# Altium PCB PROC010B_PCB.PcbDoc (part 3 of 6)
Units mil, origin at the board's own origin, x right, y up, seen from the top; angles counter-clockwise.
Board outline 3180 x 2565 mil, 6 copper layers (TOP, L2, L3, L4, L5, BOTTOM), stack 55.54 mil thick; 362 components, 264 nets, 1248 pads, 1144 vias.
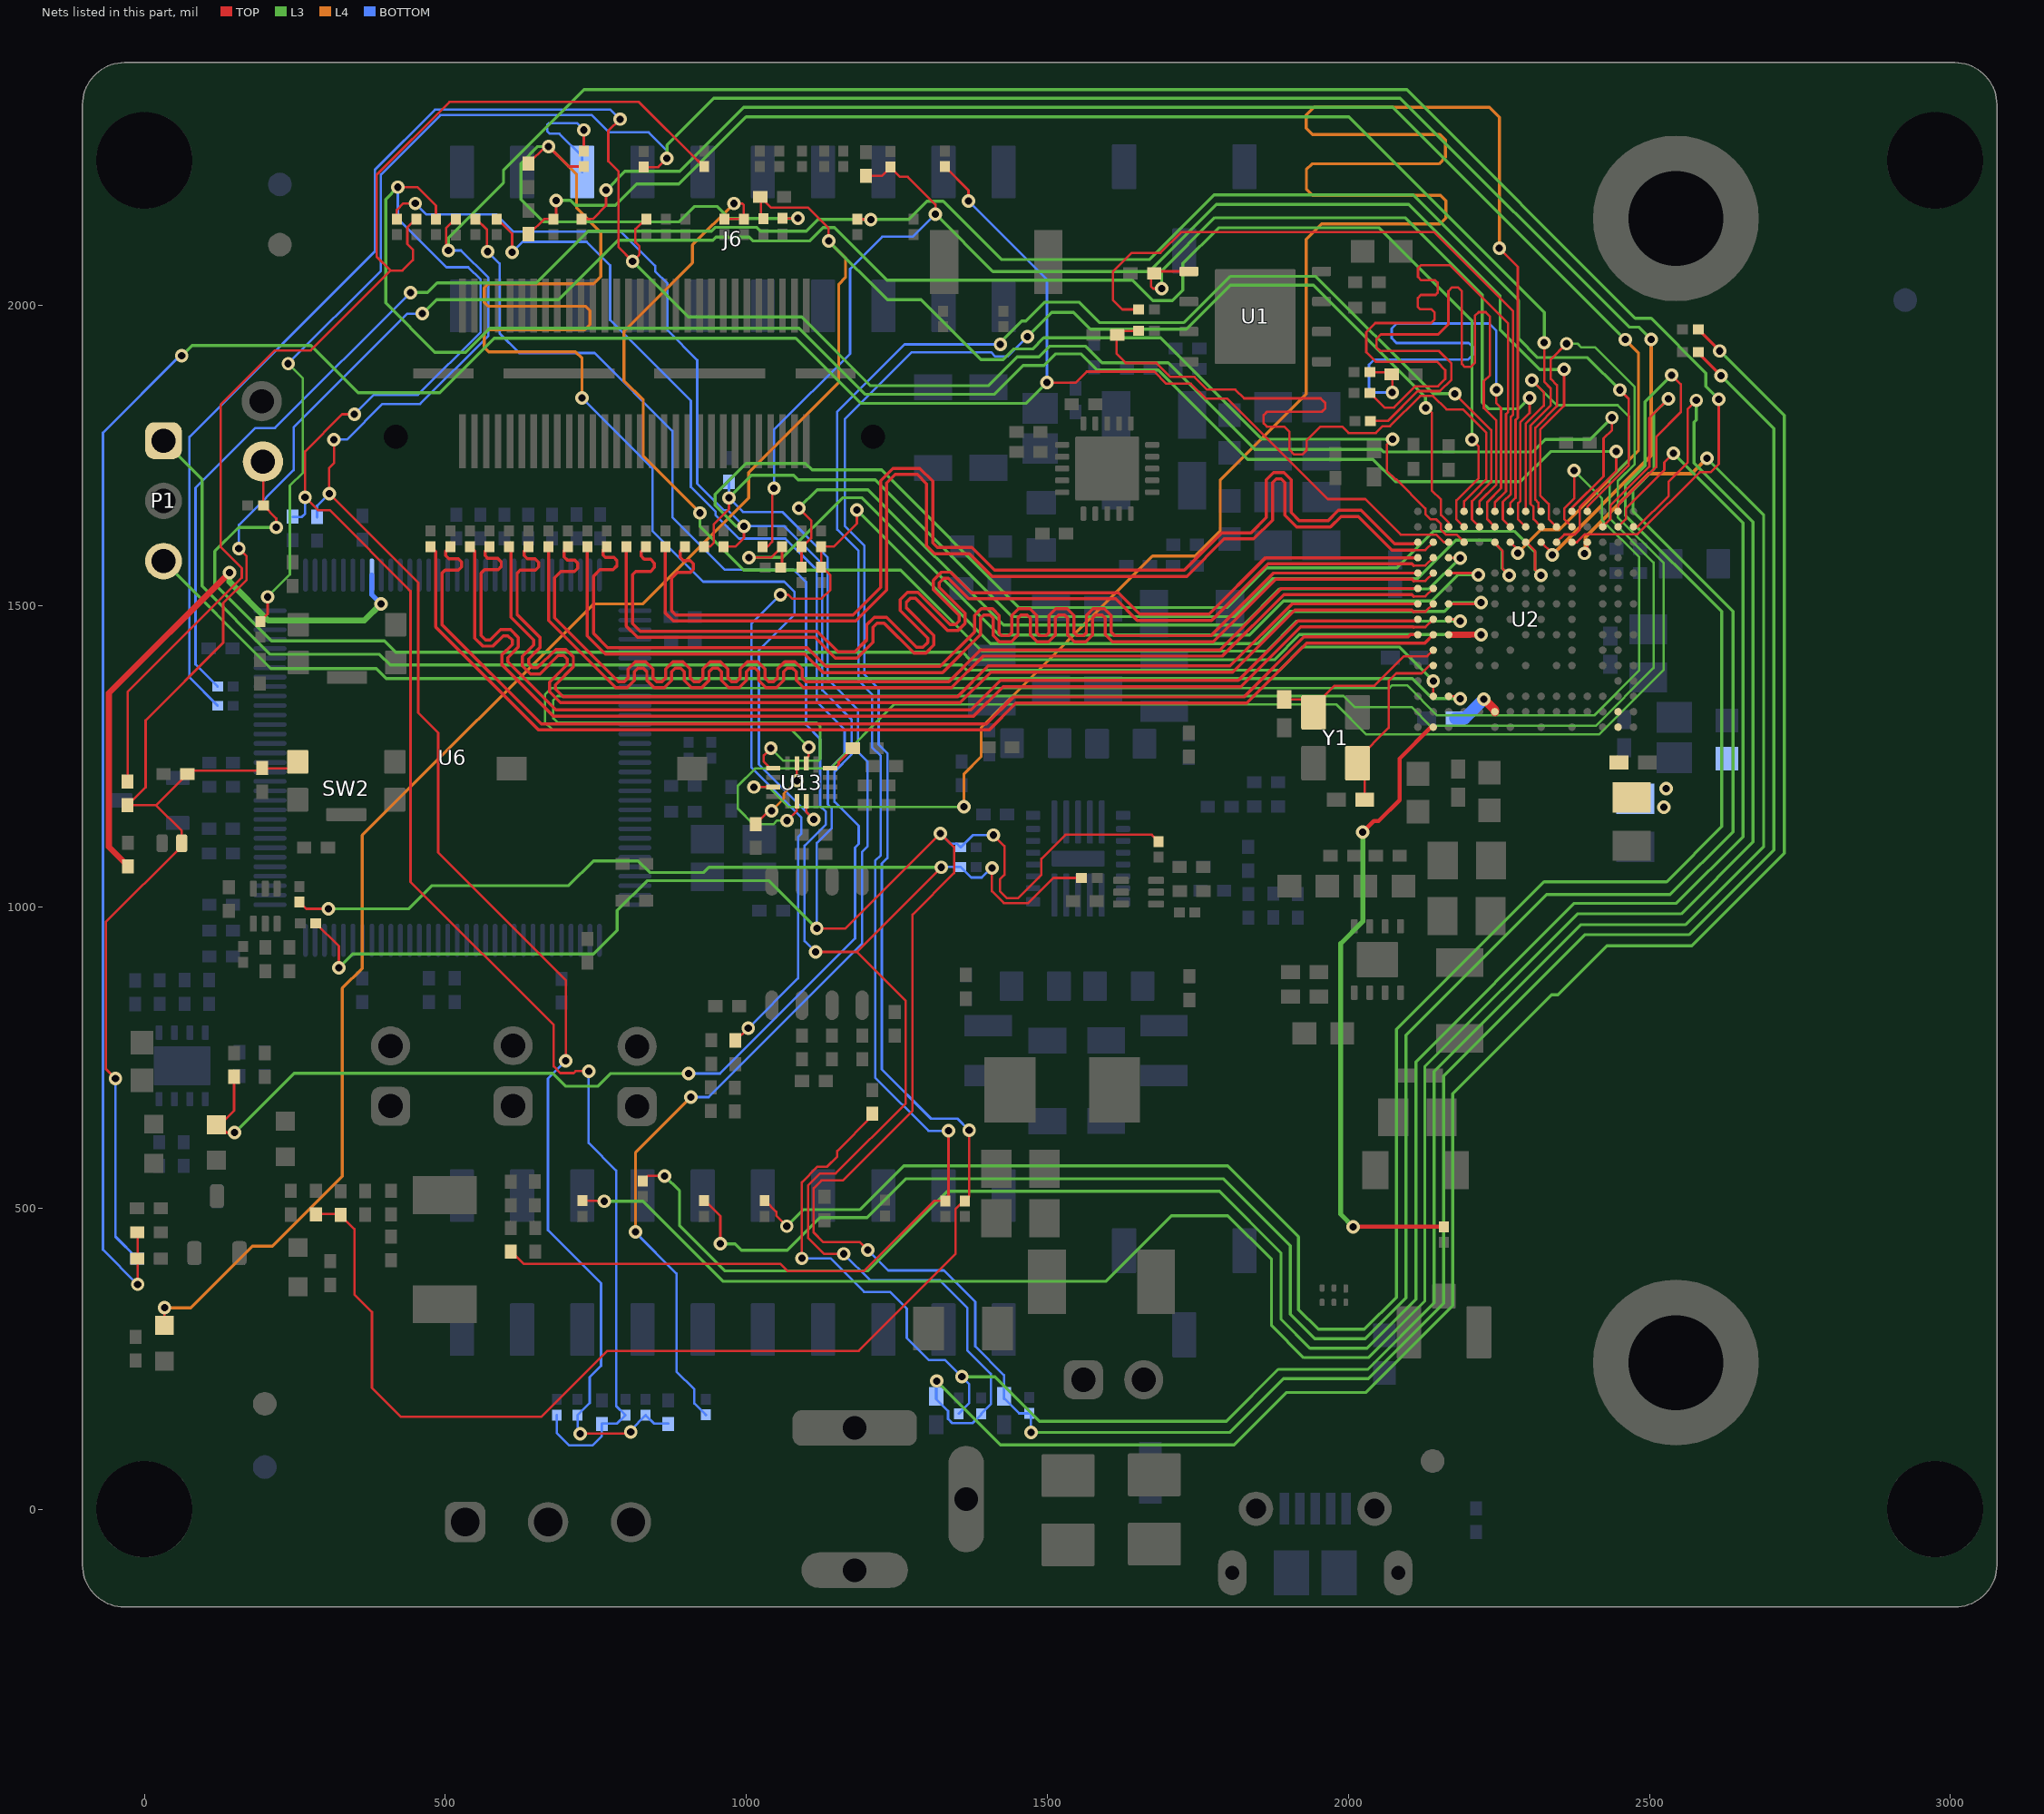
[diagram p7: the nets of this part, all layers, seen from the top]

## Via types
v1: diameter 22.4, hole 12.2, TOP to BOTTOM, tented both sides, 621 vias
v2: diameter 13.77/15.74 (per signal layer), hole 5.9, TOP to L2, tented top, 508 vias
v3: diameter 19.68, hole 7.87, TOP to BOTTOM, tented top, 7 vias
v4: diameter 19.68, hole 7.87, TOP to BOTTOM, 4 vias
v5: diameter 19.68, hole 7.87, TOP to BOTTOM, tented both sides, 3 vias
v6: diameter 19.68, hole 7.87, TOP to BOTTOM, tented bottom, 1 vias

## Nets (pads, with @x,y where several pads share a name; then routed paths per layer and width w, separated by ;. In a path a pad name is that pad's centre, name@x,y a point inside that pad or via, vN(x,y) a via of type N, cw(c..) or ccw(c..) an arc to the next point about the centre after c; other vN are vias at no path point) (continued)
AR_ANAMUX: P1.3 U2.C13 | length 2270.4
  TOP w4: U2.C13@2166.6,1349.95 2182.2,1349.95 v1(2185.95,1346.2)
  L3 w5: P1.3@31.27,1575.06 210.06,1396.27 385.08,1396.27 401.95,1379.4 2106.19,1379.4 2139.39,1346.2 v1(2185.95,1346.2)
AR_ANATEST1: R104.2 U2.P1 | length 3822.8
  TOP w4: R104.2@727.75,512.27 754,512.27 754,511.5 v1(764,511.5) ; U2.P1@2473.68,1631.44 2480.42,1631.44 2532,1683.02 2532,1706.66 2563.69,1738.34 2563.69,1827.19 v1(2578,1841.5)
  L3 w5: v1(764,511.5) 828.16,511.5 961.06,378.61 1597.42,378.61 1706.36,487.55 1799.89,487.55 1872.41,415.03 1872.41,305.11 1925.67,251.84 2032.92,251.84 2126.97,345.89 2126.97,735.23 2380.42,988.68 2552.76,988.68 2672,1107.92 2672,1639.42 2574.18,1737.25 2574.18,1805.3 2578,1809.13 v1(2578,1841.5)
AR_ANATEST2: R94.2 U2.P2 | length 3584.5
  TOP w4: R94.2@828.25,545.27 836.48,553.5 v1(864,553.5) ; U2.P2@2448.09,1631.44 2460.95,1644.3 2460.95,1661.98 2524.86,1725.89 2524.86,1738.36 v1(2540,1753.5)
  L3 w5: v1(864,553.5) 889.05,528.45 889.05,470.46 963.59,395.92 1202.19,395.92 1334.16,527.89 1786.02,527.89 1888.11,425.8 1888.11,315.63 1936.32,267.42 2030.95,267.42 2112.37,348.84 2112.37,743.08 2375.47,1006.18 2545.11,1006.18 2655.39,1116.46 2655.39,1638.11 v1(2540,1753.5)
AR_ANATEST3: R105.2 U2.P3 | length 3670
  TOP w4: R105.2@929.75,512.27 931.28,512.27 956.86,486.69 v1(956.86,440.79) ; U2.P3@2422.5,1631.44 2435.45,1644.39 2435.45,1666.95 2500,1731.5 2500,1812.5 v1(2531.5,1844)
  L3 w5: v1(956.86,440.79) 981.11,440.79 991.74,430.16 1068.11,430.16 1122.53,484.58 1200.35,484.58 1264.48,548.71 1792.67,548.71 1903.68,437.69 1903.68,323.69 1944.21,283.16 2028.16,283.16 2095.88,350.87 2095.88,787.34 2329.2,1020.66 2534.53,1020.66 2638.75,1124.88 2638.75,1491.26 2472.85,1657.16 2472.85,1692.35 2507.49,1726.99 2507.49,1819.99 v1(2531.5,1844)
AR_ANATEST4: R106.2 U2.R2 | length 3566.4
  TOP w4: R106.2@1030.25,512.27 1031.49,512.27 1049.72,494.04 1049.72,487.5 v1(1067.22,470) ; U2.R2@2448.09,1657.03 2448.09,1667.59 2511.41,1730.91 2511.41,1780.91 2552.3,1821.8 2552.3,1868.2 v1(2537,1883.5)
  L3 w5: v1(1067.22,470) 1094.81,497.59 1188.92,497.59 1261.58,570.25 1799.44,570.25 1917.36,452.33 1917.36,331.5 1950.06,298.8 2026.73,298.8 2079.84,351.91 2079.84,796.88 2325.09,1042.12 2528.62,1042.12 2620.05,1133.55 2620.05,1490.89 2459.96,1650.98 2459.96,1699.98 2492.58,1732.6 2492.58,1839.08 v1(2537,1883.5)
AR_BSS_LOGGER: R31.1 R135.1 U2.R4 | length 3430.8
  TOP w4: U2.R4@2396.91,1657.03 2396.91,1664.41 2465.49,1732.99 2465.49,1844.4 v1(2451.13,1858.76)
  TOP w5: R31.1@1182.65,2139.15 1185.37,2141.87 v1(1206.66,2141.87)
  L3 w5: v1(442,2020.5) 470.43,2020.5 486.56,2036.63 651.36,2036.63 736.99,2122.26 942.38,2122.26 949.03,2128.9 1016.89,2128.9 1023.53,2122.26 1099.51,2122.26 1119.12,2141.87 v1(1206.66,2141.87) 1269.96,2141.87 1300.19,2172.1 1326.8,2172.1 1423.44,2075.45 1669.77,2075.45 1776.94,2182.62 2107.47,2182.62 2282.52,2007.58 2282.52,1944.35 2314.39,1912.48 2397.42,1912.48 v1(2451.13,1858.76)
  BOTTOM w4: R135.1@121.79,1366.19 85,1402.98 85,1696.18 184.32,1795.5 217,1795.5 v1(442,2020.5)
AR_CS1: U2.R7 U13.10 | length 2799.2
  TOP w4: v1(1067.5,1143.73) 1083.98,1160.21 U13.10@1083.98,1175.71 ; U2.R7@2320.14,1657.03 2315.55,1661.63 2315.55,1671.77 2310.55,1676.77 2310.55,1796.15 2346.47,1832.07 2346.47,1866.84 2336.3,1877.01 2336.3,1909.5 v1(2362.38,1935.58)
  L3 w4: v1(1067.5,1143.73) 1051.19,1143.73 1045.05,1137.59 1011.49,1137.59 985.8,1163.28 985.8,1201.38 1014.57,1230.15 1139.06,1230.15 1245.47,1336.55 1980.09,1336.55 2029.86,1286.79 2416.28,1286.79 2523.8,1394.31 2523.8,1571.37 2447.53,1647.63 2447.53,1707.3 2475.65,1735.41 2475.65,1863.92 2410.04,1929.53 2387.15,1929.53 2381.1,1935.58 v1(2362.38,1935.58)
AR_GPIO_0: R164.1 R177.2 U2.N4 | length 3718.2
  TOP w4: v1(1092.13,416.62) 1092.13,542.93 1118.2,569 1134.25,569 1150.96,585.71 1150.96,594.81 1209.5,653.36 R177.2@1209.5,656.88 ; v1(2392.34,1587.4) 2396.91,1591.97 U2.N4@2396.91,1605.85
  L3 w5: v1(1358,220) 1413,220 1487.1,145.9 1797.11,145.9 1883.52,232.31 2032.28,232.31 2142.6,342.63 2142.6,727.18 2386.2,970.78 2560.31,970.78 2689.9,1100.38 2689.9,1650.98 v1(2595.65,1745.24)
  L4 w6: v1(2392.34,1587.4) 2394,1589.06 2394,1613.96 2499.54,1719.5 2569.91,1719.5 v1(2595.65,1745.24)
  BOTTOM w4: v1(1092.13,416.62) 1139.72,416.62 1195.4,360.94 1238.59,360.94 1266.44,333.09 1266.44,284.55 1302.99,248 1330,248 v1(1358,220) 1370,208 1370,175.98 R164.1@1352.75,158.73
AR_GPIO_1: R9.2 R72.2 U2.N7 | length 3760.8
  TOP w4: R72.2@192.5,1474.24 204.83,1486.57 v1(204.83,1515.16) ; R9.2@829.75,2228.73 853.51,2228.73 v1(868.03,2243.25) ; U2.N7@2320.14,1605.85 2338.45,1587.54 v1(2338.45,1585.1)
  L3 w4: v1(204.83,1515.16) 241.82,1552.15 241.82,1700.01 263.32,1721.51 263.32,1878.18 v1(239,1902.5)
  L3 w5: v1(868.03,2243.25) 868.03,2265.26 945.86,2343.08 2086.2,2343.08 2466.13,1963.16 2482.34,1963.16 v1(2503,1942.5)
  L4 w6: v1(2338.45,1585.1) 2503,1749.65 v1(2503,1942.5)
  BOTTOM w4: v1(239,1902.5) 393,2056.5 393,2216.5 491.72,2315.22 743.28,2315.22 772,2286.5 838,2286.5 868.03,2256.47 v1(868.03,2243.25) 864.75,2243.25 v1@861,2239.5
AR_GPIO_2: R8.2 R110.2 R116.1 U2.N13 | length 4502.3
  TOP w4: R110.2@-11.18,459.77 -11.12,459.71 v1(-11.12,373.5) ; R8.2@1329.55,2229.73 1369,2190.28 v1(1369,2172.5) ; v1(1499.21,1871.03) 1547.26,1871.03 1565.47,1889.24 1677.58,1889.24 1697.56,1869.26 1738.21,1869.26 1763.01,1844.46 1798.79,1844.46 1965.71,1677.54 2027.96,1677.54 2087,1618.5 2146.1,1618.5 2158.75,1605.85 U2.N13@2166.6,1605.85
  L3 w5: v1(62,1915.5) 79.02,1932.52 276.98,1932.52 355.12,1854.38 490.88,1854.38 581.05,1944.55 1081.95,1944.55 1189.89,1836.61 1464.8,1836.61 v1(1499.21,1871.03)
  BOTTOM w4: v1(-11.12,373.5) -68.67,431.05 -68.67,1787.83 59,1915.5 v1(62,1915.5) ; v1(1369,2172.5) 1499.21,2042.29 v1(1499.21,1871.03)
AR_HOSTINTR1: R10.2 R13.2 R64.2 U2.P6 | length 2434.7
  TOP w4: R64.2@1026.61,1598.73 1035.23,1598.73 1043,1606.5 1043,1692.5 v1(1046,1695.5) ; R13.2@1198.4,2214.36 1224.88,2214.36 R10.2@1239.25,2228.73 1255.34,2212.64 1268.02,2212.64 1314.1,2166.56 v1(1314.1,2150.9) ; U2.P6@2345.73,1631.44 2332.91,1644.26 2332.91,1669.44 2318.55,1683.8 2318.55,1792.83 2358.19,1832.48 v1(2358.19,1892.76)
  L3 w5: v1(1314.1,2150.9) 1409.62,2055.38 1669.06,2055.38 1780.66,2166.98 2100.41,2166.98 2252.01,2015.37 2252.01,1958.79 2318.05,1892.76 v1(2358.19,1892.76)
  BOTTOM w4: v1(1046,1695.5) 1046,1792.5 1172.2,1918.7 1172.2,2059.74 1225.75,2113.29 1276.49,2113.29 v1(1314.1,2150.9)
AR_LVDS_VALID_N: R60.2 U2.N14 | length 1930.5
  TOP w4: 2108.58,1592.91 2128.07,1592.91 U2.N14@2141.01,1605.85
  TOP w5.2: R60.2@865.55,1598.73 865.55,1487.96 878.58,1474.93 1181.43,1474.93 1233.11,1526.61 1233.11,1704.06 1247.51,1718.46 1283.9,1718.46 1299.44,1702.92 1299.44,1600.59 1313.11,1586.92 1370.46,1586.92 1408.08,1549.3 1731.83,1549.3 1793.84,1611.31 1842.55,1611.31 1873.93,1642.69 1873.93,1705.01 1880.02,1711.1 1888.64,1711.1 1894.73,1705.01 1894.73,1650.87 1914.39,1631.21 1970.21,1631.21 1987.71,1648.71 2016.79,1648.71 2072.59,1592.91 2108.58,1592.91
AR_LVDS_VALID_P: R61.2 U2.N15 | length 1930.8
  TOP w5.2: R61.2@897.75,1598.73 890,1590.98 890,1580.5 895,1575.5 906.8,1575.5 912,1570.3 912,1560.7 906.8,1555.5 885,1555.5 875.75,1546.25 875.75,1492.19 882.81,1485.13 1177.2,1485.13 1222.91,1530.84 1222.91,1708.28 1243.29,1728.66 1288.12,1728.66 1309.64,1707.14 1309.64,1604.82 1317.34,1597.12 1374.69,1597.12 1412.31,1559.5 1727.61,1559.5 1789.61,1621.51 1838.33,1621.51 1863.73,1646.91 1863.73,1709.24 1875.79,1721.3 1892.87,1721.3 1904.93,1709.24 1904.93,1655.1 1918.62,1641.41 1965.98,1641.41 1983.48,1658.91 2021.02,1658.91 2076.82,1603.11 2108.58,1603.11 2111.32,1605.85 U2.N15@2115.42,1605.85
AR_LVDSCSI0_N: R48.2 U2.G14 | length 1930.5
  TOP w5.2: R48.2@475.61,1598.73 484,1590.34 484,1465.08 655.05,1294.04 1402.98,1294.04 1447.73,1338.79 1830.98,1338.79 1930.51,1438.32 2127.02,1438.32 U2.G14@2141.01,1452.31
AR_LVDSCSI0_P: R49.2 U2.G15 | length 1930.6
  TOP w5.2: R49.2@508.25,1598.73 500.58,1591.06 500.58,1583.7 505.78,1578.5 521.8,1578.5 527,1573.3 527,1564.7 521.8,1559.5 499.4,1559.5 494.2,1554.3 494.2,1469.31 659.27,1304.24 1398.75,1304.24 1443.5,1348.99 1826.76,1348.99 1926.29,1448.52 2099.22,1448.52 2103.01,1452.31 U2.G15@2115.42,1452.31
AR_LVDSCSI1_N: R50.2 U2.H14 | length 1931
  TOP w4: 2108.32,1464.96 2128.07,1464.96 U2.H14@2141.01,1477.9
  TOP w5.2: R50.2@540.75,1598.73 541.77,1598.73 549,1591.5 549,1446.77 562.37,1433.4 578.91,1433.4 596.01,1450.5 604.01,1450.5 611.06,1443.45 611.06,1436.09 593.64,1418.67 593.64,1402.87 679.21,1317.3 1377.61,1317.3 1426.4,1366.09 1821.53,1366.09 1920.74,1465.3 2107.98,1465.3 2108.32,1464.96
AR_LVDSCSI1_P: R51.2 U2.H15 | length 1931
  TOP w5.2: R51.2@573.25,1598.73 566,1591.48 566,1583.5 570,1579.5 586.43,1579.5 592.87,1573.06 592.87,1565.7 587.67,1560.5 565,1560.5 559.2,1554.7 559.2,1450.99 566.59,1443.6 574.68,1443.6 591.78,1460.7 608.24,1460.7 621.26,1447.68 621.26,1431.86 603.84,1414.44 603.84,1407.1 683.44,1327.5 1373.39,1327.5 1422.17,1376.28 1817.3,1376.28 1916.52,1475.5 2113.02,1475.5 U2.H15@2115.42,1477.9
AR_LVDSCSI2_N: R54.2 U2.K14 | length 1930.8
  TOP w4: 2108.32,1516.14 2128.07,1516.14 U2.K14@2141.01,1529.08
  TOP w5.2: R54.2@671.35,1598.73 671.35,1476.15 783.2,1364.3 801.86,1364.3 813.92,1376.36 813.92,1391.01 820.01,1397.1 828.63,1397.1 834.72,1391.01 834.72,1376.36 846.78,1364.3 863.86,1364.3 875.92,1376.36 875.92,1391.01 882.01,1397.1 890.63,1397.1 896.72,1391.01 896.72,1376.36 908.78,1364.3 925.86,1364.3 937.92,1376.36 937.92,1391.01 944.01,1397.1 952.63,1397.1 958.72,1391.01 958.72,1376.36 970.78,1364.3 987.86,1364.3 999.92,1376.36 999.92,1391.01 1006.01,1397.1 1014.63,1397.1 1020.72,1391.01 1020.72,1376.36 1032.78,1364.3 1049.86,1364.3 1061.92,1376.36 1061.92,1391.01 1068.01,1397.1 1076.63,1397.1 1082.72,1391.01 1082.72,1376.36 1094.78,1364.3 1340.79,1364.3 1393.29,1416.8 1790.68,1416.8 1892.76,1518.88 2105.58,1518.88 2108.32,1516.14
AR_LVDSCSI2_P: R55.2 U2.K15 | length 1930.8
  TOP w5.2: R55.2@703.85,1598.73 697,1591.88 697,1581.7 702.2,1576.5 714.8,1576.5 720,1571.3 720,1562.7 714.8,1557.5 692,1557.5 681.55,1547.05 681.55,1480.38 787.43,1374.5 797.63,1374.5 803.72,1380.59 803.72,1395.24 815.78,1407.3 832.86,1407.3 844.92,1395.24 844.92,1380.59 851.01,1374.5 859.63,1374.5 865.72,1380.59 865.72,1395.24 877.78,1407.3 894.86,1407.3 906.92,1395.24 906.92,1380.59 913.01,1374.5 921.63,1374.5 927.72,1380.59 927.72,1395.24 939.78,1407.3 956.86,1407.3 968.92,1395.24 968.92,1380.59 975.01,1374.5 983.63,1374.5 989.72,1380.59 989.72,1395.24 1001.78,1407.3 1018.86,1407.3 1030.92,1395.24 1030.92,1380.59 1037.01,1374.5 1045.63,1374.5 1051.72,1380.59 1051.72,1395.24 1063.78,1407.3 1080.86,1407.3 1092.92,1395.24 1092.92,1380.59 1099.01,1374.5 1336.57,1374.5 1389.07,1427 1786.46,1427 1888.54,1529.08 U2.K15@2115.42,1529.08
AR_LVDSCSI3_N: R56.2 U2.L14 | length 1930.7
  TOP w4: 2108.32,1541.73 2128.07,1541.73 U2.L14@2141.01,1554.67
  TOP w5.2: R56.2@735.75,1598.73 735.76,1450.3 765.56,1420.5 1096.79,1420.5 1127.79,1389.5 1326.03,1389.5 1389.09,1452.56 1389.09,1480.1 1394.29,1485.3 1404.69,1485.3 1409.89,1480.1 1409.89,1450.81 1420.2,1440.5 1439.92,1440.5 1451.09,1451.67 1451.09,1480.1 1456.29,1485.3 1466.69,1485.3 1471.89,1480.1 1471.89,1451.68 1483.07,1440.5 1501.91,1440.5 1513.09,1451.68 1513.09,1480.1 1518.29,1485.3 1528.69,1485.3 1533.89,1480.1 1533.89,1451.67 1545.06,1440.5 1563.91,1440.5 1575.09,1451.68 1575.09,1480.1 1580.29,1485.3 1590.69,1485.3 1595.89,1480.1 1595.89,1452.56 1607.95,1440.5 1775.76,1440.5 1879.73,1544.47 2105.58,1544.47 2108.32,1541.73
AR_LVDSCSI3_P: R57.2 U2.L15 | length 1930.7
  TOP w5.2: R57.2@768.05,1598.73 762,1592.68 762,1584.5 766,1580.5 779.8,1580.5 785,1575.3 785,1566.7 778.8,1560.5 757,1560.5 745.96,1549.46 745.96,1454.53 769.79,1430.7 1101.02,1430.7 1132.02,1399.7 1321.8,1399.7 1378.89,1456.79 1378.89,1484.33 1390.06,1495.5 1408.92,1495.5 1420.09,1484.33 1420.09,1455.04 1424.43,1450.7 1435.69,1450.7 1440.89,1455.9 1440.89,1484.33 1452.06,1495.5 1470.92,1495.5 1482.09,1484.33 1482.09,1455.91 1487.3,1450.7 1497.68,1450.7 1502.89,1455.91 1502.89,1484.33 1514.06,1495.5 1532.92,1495.5 1544.09,1484.33 1544.09,1455.9 1549.29,1450.7 1559.68,1450.7 1564.89,1455.91 1564.89,1484.33 1576.06,1495.5 1594.92,1495.5 1606.09,1484.33 1606.09,1456.79 1612.18,1450.7 1771.53,1450.7 1875.5,1554.67 U2.L15@2115.42,1554.67
AR_LVDSCSI_CLK_N: R52.2 U2.J14 | length 1930.5
  TOP w4: 2108.32,1490.55 2128.07,1490.55 U2.J14@2141.01,1503.49
  TOP w5.2: R52.2@605.75,1598.73 609,1595.48 609,1481.5 646.75,1443.75 646.75,1435.13 627.95,1416.33 627.95,1400.51 641.29,1387.17 657.11,1387.17 687.72,1417.78 696.28,1417.78 702.43,1411.63 702.43,1403.07 672.83,1373.47 672.83,1357.67 691.2,1339.3 1355.15,1339.3 1405.98,1390.12 1807.86,1390.12 1911.03,1493.29 2105.58,1493.29 2108.32,1490.55
AR_LVDSCSI_CLK_P: R53.2 U2.J15 | length 1930.2
  TOP w5.2: R53.2@638.25,1598.73 631,1591.48 631,1583.7 636.2,1578.5 648.78,1578.5 655,1572.28 655,1564.7 649.8,1559.5 624.4,1559.5 619.2,1554.3 619.2,1485.73 656.95,1447.98 656.95,1430.9 638.15,1412.1 638.15,1404.74 645.52,1397.37 652.88,1397.37 683.49,1427.98 700.51,1427.98 712.63,1415.86 712.63,1398.84 683.03,1369.24 683.03,1361.9 695.43,1349.5 1350.93,1349.5 1401.75,1400.32 1803.64,1400.32 1906.8,1503.49 U2.J15@2115.42,1503.49
AR_LVDSCSI_FRCLK_N: R58.2 U2.M14 | length 1930.8
  TOP w4: 2108.32,1567.32 2128.07,1567.32 U2.M14@2141.01,1580.26
  TOP w5.2: R58.2@800.55,1598.73 800.55,1466.51 819.26,1447.8 1113.7,1447.8 1148,1413.5 1184.14,1413.5 1210.39,1439.74 1210.39,1464.72 1216.94,1471.27 1228.79,1471.27 1277.87,1422.19 ; 1277.88,1422.19 1278.69,1421.38 1297.65,1421.38 1311.47,1435.2 1311.47,1451.01 1310.59,1451.89 1265.73,1496.76 1265.73,1506.32 1271.96,1512.55 1280.96,1512.55 1334.46,1459.05 1351.54,1459.05 1363.6,1471.11 1363.6,1488.19 1320.53,1531.26 1320.53,1538.39 1328.13,1545.99 1335.26,1545.99 1369.33,1511.92 1613.53,1511.92 1649.29,1476.16 1772.79,1476.16 1866.69,1570.06 2105.58,1570.06 2108.32,1567.32
AR_LVDSCSI_FRCLK_P: R59.2 U2.M15 | length 1930.3
  TOP w5.2: R59.2@833.05,1598.73 825,1590.68 825,1582.7 830.2,1577.5 840.92,1577.5 847.24,1571.18 847.24,1563.82 840.92,1557.5 816,1557.5 810.75,1552.25 810.75,1470.74 823.49,1457.99 1117.93,1457.99 1152.23,1423.7 1179.92,1423.7 1200.19,1443.97 1200.19,1468.94 1212.72,1481.47 1233.02,1481.47 1282.91,1431.58 1293.43,1431.58 1301.28,1439.42 1301.28,1446.78 1255.53,1492.53 1255.53,1510.54 1267.74,1522.75 1285.19,1522.75 1338.69,1469.25 1347.31,1469.25 1353.4,1475.34 1353.4,1483.96 1310.33,1527.03 1310.33,1542.61 1323.91,1556.19 1339.49,1556.19 1373.56,1522.12 1617.76,1522.12 1653.52,1486.36 1768.56,1486.36 1862.46,1580.26 U2.M15@2115.42,1580.26
AR_MCUCLKOUT: R25.1 U2.N9 | length 2473.2
  TOP w4: R25.1@726.25,2142.71 744.9,2142.71 767,2164.81 v1(767,2190.5) ; U2.N9@2268.96,1605.85 2281.19,1593.62 v1(2281.19,1587.85)
  L3 w5: v1(767,2190.5) 798.36,2221.86 889.32,2221.86 995.82,2328.37 2074.05,2328.37 v1(2459.96,1942.46)
  L4 w5: v1(2281.19,1587.85) 2319.84,1626.5 2350.43,1626.5 2481.77,1757.84 2481.77,1920.65 v1(2459.96,1942.46)
AR_MISO1: U2.P5 U13.2 | length 2887.4
  TOP w4: U13.2@1099.73,1238.71 1099.73,1247.06 1103.57,1250.89 v1(1103.57,1265.52) ; U2.P5@2371.32,1631.44 2358.82,1643.94 2358.82,1662.32 2375,1678.5 v1(2375,1725)
  L3 w4: v1(1103.57,1265.52) 1074.7,1294.39 677.98,1294.39 665.41,1306.96 665.41,1352.64 676.51,1363.74 2068.2,1363.74 2072.78,1368.32 2097.46,1368.32 2147.38,1318.4 2408.4,1318.4 2483.17,1393.17 2483.17,1581.06 2421.18,1643.05 2421.18,1678.82 v1(2375,1725)
AR_MOSI1: U2.R8 U13.5 | length 3449.3
  TOP w4: v1(1040.7,1263.94) 1028.78,1252.02 1028.78,1241.41 1039.36,1230.83 U13.5@1044.61,1230.83 ; U2.R8@2294.55,1657.03 2294.55,1802.77 2324.54,1832.77 2324.54,1855.08 v1(2304.72,1874.9)
  L3 w4: v1(1040.7,1263.94) 1061.69,1242.95 1119.65,1242.95 1122.59,1245.9 1122.59,1300.34 1116.76,1306.18 686.78,1306.18 679.28,1313.68 679.28,1343.46 686.33,1350.51 1991.94,1350.51 2010.64,1331.81 2105.54,1331.81 2136.32,1301.02 2411.06,1301.02 2506.93,1396.89 2506.93,1572.14 2434.1,1644.97 2434.1,1711.17 2465.94,1743.02 2465.94,1814.9 2447.33,1833.51 2346.11,1833.51 v1(2304.72,1874.9)
AR_MSS_LOGGER: R26.1 R136.1 U2.R5 | length 3858.3
  TOP w4: v1(790,2308.5) 770.75,2289.25 770.75,2238.75 787.37,2222.13 787.37,2096.13 v1(811,2072.5) 822.45,2083.95 822.45,2097.21 815.72,2103.95 815.72,2125.93 832.5,2142.71 R26.1@834.11,2142.71 ; U2.R5@2371.32,1657.03 2371.32,1662.82 2423.95,1715.45 2423.95,1778.54 2437.81,1792.4 v1(2437.81,1812.83)
  L3 w5: v1(811,2072.5) 903.55,1979.95 1092.11,1979.95 1206.2,1865.87 1402.01,1865.87 1449.72,1913.58 1486.35,1913.58 1504.32,1931.55 1563.3,1931.55 1590.81,1904.04 1700.57,1904.04 1844.52,1760.09 2054.08,1760.09 2058.42,1755.74 2306.14,1755.74 2327,1776.61 2401.58,1776.61 v1(2437.81,1812.83)
  BOTTOM w4: R136.1@121.79,1334.29 75,1381.08 75,1780.78 383,2088.78 383,2224.49 482.72,2324.22 774.28,2324.22 v1(790,2308.5)
AR_NERR_OUT: DS1.2 R7.2 R19.1 R91.1 U2.N8 | length 4919.1
  TOP w4: R91.1@149,718.2 149,662.1 124.73,637.83 137.06,625.5 v1(150,625.5) ; R19.1@419.25,2142.71 419.25,2157.75 430,2168.5 v1(450,2168.5) ; R7.2@962.11,1598.73 981.73,1598.73 995.94,1612.94 v1(995.94,1632.56) ; U2.N8@2294.55,1605.85 2295.65,1605.85 2310,1591.5 2310,1560.45 v1(2319.65,1550.8)
  L3 w5: v1(150,625.5) 248.65,724.15 678.65,724.15 700.35,702.45 752.8,702.45 773.85,723.5 v1(904,723.5) ; v1(995.94,1632.56) 982.51,1632.56 948,1667.07 948,1685.77 999.12,1736.89 1098.3,1736.89 1109.23,1725.96 1224.73,1725.96 1453.32,1497.37 1798.45,1497.37 1864.47,1563.39 2080.69,1563.39 2141.36,1624.05 2275.55,1624.05 2310,1589.6 2310,1560.45 v1(2319.65,1550.8)
  BOTTOM w4: v1(450,2168.5) 468.33,2150.17 584.66,2150.17 613.16,2121.66 791.6,2121.66 848.52,2064.74 848.52,2055.72 869.16,2035.08 869.16,1957.7 918.47,1908.39 918.47,1703.46 962.96,1658.97 969.53,1658.97 v1(995.94,1632.56) 1063.08,1632.56 1126.12,1569.52 1126.12,1360.38 1174.8,1311.7 1174.8,1253.49 1146.37,1225.06 1146.37,1174.96 1186.69,1134.64 1186.69,1104.83 1180.54,1098.69 1180.54,947.84 956.2,723.5 v1(904,723.5)
AR_NERRIN: R16.1 R24.1 U2.P7 | length 2305.9
  TOP w4: R16.1@638.2,2118.25 639.75,2118.25 664.21,2142.71 R24.1@679.75,2142.71 684,2146.96 v1(684,2173.5) ; U2.P7@2320.14,1631.44 2307.55,1644.03 2307.55,1664.36 2302.55,1669.36 2302.55,1799.46 2336,1832.91 2336,1861.75 2325.3,1872.46 v1(2325.3,1937.18)
  L3 w5: v1(684,2173.5) 708.06,2173.5 716.11,2165.45 782.52,2165.45 817.7,2200.63 888.09,2200.63 999.73,2312.27 2000.58,2312.27 2325.3,1987.56 v1(2325.3,1937.18)
AR_NRST: C11.2 D2.2 R74.1 R77.2 R160.1 SW2.4 U2.P12 | length 4567.5
  TOP w4: v1(-48,715.5) -64,731.5 -64,975.35 62.05,1101.4 D2.2@62.05,1106.06 62.05,1126.47 19.36,1169.16 ; v1(157,1595.5) 169.9,1582.6 169.9,1543.6 130.99,1504.7 130.99,1439.05 2,1310.06 2,1198.9 R77.2@-27.74,1169.16 19.36,1169.16 ; SW2.4@254.64,1241.26 243.93,1230.55 195.7,1230.55 191.65,1226.5 76.69,1226.5 R74.1@71.34,1221.14 19.36,1169.16 ; U2.P12@2192.19,1631.44 2192.1,1631.44 2179.59,1643.95 2179.59,1675.35 2216.39,1712.15 2216.39,1765.01 v1(2205.25,1776.15)
  L3 w5: v1(462,1985.5) 485.14,2008.64 687.94,2008.64 786.65,2107.34 944.35,2107.34 949.73,2112.72 1004.64,2112.72 1011.16,2106.21 1104.74,2106.21 1127.24,2128.71 1146.35,2128.71 1233.93,2041.14 1641.05,2041.14 1675.09,2007.09 1707.54,2007.09 1724.93,2024.47 1724.93,2068.73 1784.2,2128 2051.11,2128 2205.25,1973.86 v1(2205.25,1776.15)
  BOTTOM w4: v1(-48,715.5) -48,452.71 R160.1@-11.2,415.91 ; v1(157,1595.5) 157,1634.74 248,1725.74 248,1796.51 436.99,1985.5 v1(462,1985.5)
AR_NRST_MCU: R2.2 R20.1 R77.1 | length 2040
  TOP w4: R77.1@-27.74,1207.75 R77.1@-27.74,1208.53 -27.74,1357.28 161.9,1546.92 161.9,1562.83 126.94,1597.78 126.94,1834.81 216.64,1924.5 276.3,1924.5 408.8,2057 ; R20.1@452.11,2142.71 450.87,2142.71 436.84,2128.68 436.84,2101.15 446.2,2091.79 446.2,2074.7 428.5,2057 408.8,2057 ; 408.8,2057 386,2079.8 386,2215.99 507.01,2337 821.54,2337 918.88,2239.66 ; 918.88,2239.66 928.81,2229.73 R2.2@930.05,2229.73 920.12,2239.66 918.88,2239.66
AR_NRST_XDS: R80.1 U6.40 | length 942.6
  TOP w10: R80.1@-27.26,1068.25 -59,1099.99 -59,1355.42 v1(141.26,1555.68)
  L3 w10: v1(141.26,1555.68) 141.26,1540.43 205.74,1475.95 365.45,1475.95 v1(393,1503.5)
  BOTTOM w8: U6.40@377.93,1551.19 377.93,1518.57 v1(393,1503.5)
AR_OSC_CLKOUT: R111.1 U2.A14 | length 1059.7
  TOP w7.08: v1(2008,469.16) R111.1@2158.86,469.16 ; v1(2024,1124.5) 2042.22,1142.72 2050.13,1142.72 2085,1177.59 2085,1246.5 2137.27,1298.77 U2.A14@2141.01,1298.77
  L3 w8: v1(2008,469.16) 1987.13,490.03 1987.13,939.36 2024,976.23 v1(2024,1124.5)
AR_PMIC_CLKOUT_SOP2: R97.1 R98.1 R109.2 U2.P13 | length 4362.4
  TOP w4: R97.1@285,490.25 324.11,490.25 349,465.36 349,356.5 378,327.5 378,201.49 425.99,153.5 659.51,153.5 769.07,263.06 1186.64,263.06 1347.44,423.86 1347.44,498.55 1360.96,512.07 R109.2@1362.85,512.07 1370.05,519.28 v1(1370.05,629.15) ; v1(2128.34,1829.19) 2130.31,1829.19 2138.4,1821.1 2138.4,1691.94 2153.85,1676.49 2153.85,1650.79 2166.6,1638.04 U2.P13@2166.6,1631.44
  L3 w5: v1(1467,1947.5) 1506.93,1987.44 1543.66,1987.44 1571.61,1959.49 1730.65,1959.49 1803.9,2032.73 1942.34,2032.73 2128.34,1846.73 v1(2128.34,1829.19)
  BOTTOM w4: v1(1370.05,629.15) 1350.6,648.61 1306.78,648.61 1225.06,730.32 1225.06,1072.24 1234.27,1081.45 1234.27,1255.38 1219.8,1269.85 1219.8,1362.91 1195.95,1386.76 1195.95,1600.47 1163.51,1632.91 1163.51,1810.14 1274.67,1921.3 1406.63,1921.3 1413.63,1914.3 1433.8,1914.3 v1(1467,1947.5)
AR_QSPI_CS: R38.1 U1.1 U2.P8 | length 1249.6
  TOP w4: v1(1690.01,2027.11) 1675.67,2027.11 1672.36,2030.43 1672.36,2047.32 R38.1@1677.37,2052.34 1680.71,2055.68 U1.1@1734.99,2055.68 ; U2.P8@2294.55,1631.44 2282.05,1643.94 2282.05,1670.71 2285.78,1674.44 2285.78,1805.32 2301,1820.54 v1(2301,1845.5)
  L3 w5: v1(1690.01,2027.11) 1690.01,2056.68 1778.05,2144.71 2094.4,2144.71 2222.37,2016.74 2222.37,1838.01 2232.8,1827.57 2283.07,1827.57 v1(2301,1845.5)
AR_QSPI_D0: R45.2 U2.R11 | length 1154.6
  TOP w4: R45.2@2036.77,1807.35 2036.92,1807.5 2065.8,1807.5 2115.18,1856.87 2152.14,1856.87 2171.08,1875.81 2171.08,1902.99 2150.52,1923.55 2052.86,1923.55 2046.91,1929.5 2046.91,1943.74 2054.11,1950.94 2149.19,1950.94 2166.23,1967.98 2166.23,2022.98 2172.44,2029.19 2181.64,2029.19 2188.41,2022.42 2188.41,1901.93 2193.37,1896.97 2203.3,1896.97 2210.03,1903.7 2210.03,1981.59 2216.33,1987.9 2228.07,1987.9 2235.25,1980.72 2235.25,1883.57 2225,1873.32 2225,1828.83 2245.41,1808.42 2245.41,1701.17 2217.78,1673.54 U2.R11@2217.78,1657.03
AR_QSPI_D1: R39.1 U2.P9 | length 1213.3
  TOP w4: R39.1@1651.79,1992.45 1624.55,1992.45 1608.69,2008.31 1608.69,2055.09 1639.97,2086.37 1687.99,2086.37 1722.39,2120.78 2142.66,2120.78 2273.38,1990.06 2273.38,1817.75 2269.78,1814.16 2269.78,1686.04 2256.46,1672.72 2256.46,1643.94 U2.P9@2268.96,1631.44
AR_QSPI_D2: R42.1 R43.1 U2.R12 | length 1219.1
  TOP w4: R42.1@1651.79,1956.85 1621.64,1956.85 1615,1950.21 1615,1918.83 1630.2,1903.63 1681.2,1903.63 1704.4,1880.44 1744.17,1880.44 1765.2,1859.41 1812.22,1859.41 1826.91,1844.73 1953.95,1844.73 1961.78,1836.9 1961.78,1828.53 1955.82,1822.58 1864.87,1822.58 1859.14,1816.84 1859.14,1803.04 1864.43,1797.74 1893.14,1797.74 1902.09,1788.79 1902.09,1759.76 1910.32,1751.53 1923.67,1751.53 1930.66,1758.53 1930.66,1774.52 1953.88,1797.74 1989.95,1797.74 2000.3,1787.39 2045.88,1787.39 2057.08,1798.59 2069.18,1798.59 2119.46,1848.87 2140.66,1848.87 2163.03,1826.5 2190.01,1826.5 2229.26,1787.25 2229.26,1711.02 2192.19,1673.95 U2.R12@2192.19,1657.03
AR_QSPI_D3: R40.2 R41.1 U2.P10 | length 1024
  TOP w4: R40.2@2035.77,1888.35 2068.88,1888.35 2073,1884.23 v1(2073,1854.5) ; U2.P10@2243.37,1631.44 2243.3,1631.44 2230.59,1644.15 2230.59,1672.45 2253.65,1695.51 2253.65,1828.97 2245.76,1836.86 v1(2245.76,1859.34)
  BOTTOM w4: v1(2073,1854.5) 2042.75,1854.5 2034.39,1862.86 2034.39,1900.71 2042.76,1909.08 2198.68,1909.08 2206.97,1917.38 2206.97,1929.99 2200.13,1936.83 2079.88,1936.83 2071.9,1944.81 2071.9,1960.48 2080.58,1969.15 2233.97,1969.15 2245.76,1957.36 v1(2245.76,1859.34)
AR_QSPI_SCLK: R44.2 U2.R10 | length 1144.7
  TOP w4: R44.2@2035.77,1853.85 2060.12,1829.5 2076,1829.5 2111.37,1864.87 2148.83,1864.87 2160.89,1876.93 2160.89,1891.87 2147.21,1905.55 2045.47,1905.55 2029.7,1921.32 2029.7,1954.89 2044.6,1969.79 2137.46,1969.79 2143.22,1975.55 2143.22,1987.42 2138.01,1992.63 2119.35,1992.63 2115.41,1996.57 2115.41,2011.44 2120.51,2016.54 2144.73,2016.54 2148.23,2020.04 2148.23,2036.83 2144.1,2040.97 2121.07,2040.97 2115.62,2046.41 2115.62,2060.88 2120.93,2066.19 2168.16,2066.19 2265.38,1968.97 2265.38,1822.26 2261.78,1818.67 2261.78,1690.54 2243.37,1672.13 U2.R10@2243.37,1657.03
AR_RESERVED: C8.1 TP2.1 U2.G13 | length 2518.4
  TOP w4: TP2.1@196.94,1739.77 197.7,1739.01 C8.1@197.68,1666.75 219,1645.45 v1(219,1630.5)
  TOP w10: U2.G13@2166.6,1452.31 2202.26,1452.31 2202.35,1452.4 v1(2220.55,1452.4)
  L3 w5: v1(219,1630.5) 156.57,1630.5 116.95,1590.88 116.95,1536.29 211.11,1442.13 398.67,1442.13 417.68,1423.12 1359.33,1423.12 1371.76,1410.69 1877.03,1410.69 1918.75,1452.4 v1(2220.55,1452.4)
AR_RS232RX: R33.1 R129.1 R166.1 R168.1 R172.1 U2.N5 | length 5544.5
  TOP w4: v1(315,1776.5) 315,1737.35 307,1729.35 v1(307,1686.5) 454.92,1538.58 454.92,1322.58 488.09,1289.41 488.09,1090.48 700,878.56 v1(700,744.5) ; v1(505,2090.5) 501.12,2094.38 501.12,2127.24 516.15,2142.27 R33.1@517.39,2142.27 ; v1(724,125.5) 805,125.5 v1(808,128.5) ; U2.N5@2371.32,1605.85 2379.52,1605.85 2392.81,1619.14 2480.64,1619.14 2583.6,1722.1 2601.85,1722.1 2615.33,1735.57 2615.33,1843.17 v1(2615.2,1843.3)
  L3 w5: v1(505,2090.5) 505,2111.19 596.5,2202.69 596.5,2223.43 730.51,2357.44 2097.02,2357.44 2476.51,1977.94 2502.99,1977.94 2593.95,1886.98 2593.95,1864.55 v1(2615.2,1843.3)
  BOTTOM w4: R129.1@287,1647.4 R129.1@287,1648.18 287,1666.5 v1(307,1686.5) ; v1(315,1776.5) 336.63,1776.5 395.63,1835.5 458.16,1835.5 571.52,1948.86 571.52,2044.98 526,2090.5 v1(505,2090.5) ; v1(700,744.5) 670.55,715.05 670.55,463.47 758.52,375.5 758.52,238.03 739.69,219.2 739.69,176.35 R168.1@719.63,156.29 719.63,129.87 v1(724,125.5) ; v1(808,128.5) 808,131.54 R166.1@832.75,156.29 846.79,142.25 R172.1@870.18,142.25
AR_RS232TX: R21.1 R128.1 R167.1 R169.1 R173.1 U2.N6 | length 5569.5
  TOP w4: v1(349,1818.5) 328.58,1818.5 267,1756.92 v1(267,1680.5) 288.25,1659.25 307.75,1659.25 442.26,1524.74 442.26,1041.74 679.96,804.04 679.96,735.42 691.03,724.36 713.05,724.36 716.2,727.5 v1(738,727.5) ; v1(421,2195.5) 453.88,2195.5 484.35,2165.02 R21.1@484.35,2142.71 ; U2.N6@2345.73,1605.85 2358.73,1618.85 2376.41,1618.85 2384.09,1626.53 2384.09,1663.59 2445,1724.5 v1(2445,1756.5)
  L3 w5: v1(421,2195.5) 400.95,2175.45 400.95,2003.12 482.62,1921.45 533.95,1921.45 573.9,1961.4 1087.72,1961.4 1197.62,1851.5 1411.43,1851.5 1459.48,1899.55 1494.23,1899.55 1513.23,1918.55 1555.96,1918.55 1582.83,1891.67 1684.5,1891.67 1832.53,1743.64 2040.86,1743.64 2078.18,1706.32 2285.92,1706.32 2336.1,1756.5 v1(2445,1756.5)
  BOTTOM w4: R128.1@246.5,1647.75 261.21,1647.75 267,1653.54 v1(267,1680.5) ; v1(349,1818.5) 381.03,1850.53 454.48,1850.53 558.61,1954.66 558.61,2041.86 537.97,2062.5 502,2062.5 421,2143.5 v1(421,2195.5) ; R169.1@685.13,156.29 685.13,126.82 706.05,105.9 744.51,105.9 759.88,121.27 R173.1@759.88,141.47 759.88,142.25 785.09,142.25 R167.1@799.13,156.29 783.78,171.64 783.78,562.46 738,608.23 v1(738,727.5)
AR_SCL: R22.1 R144.1 R163.1 R171.1 R180.1 R185.1 R197.1 | length 7549.2
  TOP w4: R185.1@257.83,1008.23 269.06,997 v1(306,997) ; R22.1@550.11,2142.71 551.35,2142.71 569.34,2124.72 569.34,2089.16 v1(570,2088.5) ; v1(1115,925.5) 1183.6,925.5 ; v1(1162,424) 1128.98,424 1102.39,450.59 1102.39,537.71 1122.33,557.65 1148.29,557.65 1264.8,674.16 1264.8,844.3 1183.6,925.5 ; v1(1323.73,1065.99) 1183.42,925.68 1183.6,925.5 ; v1(1408,1065) 1408,1026.26 1427.52,1006.74 1468.26,1006.74 1509.85,1048.33 R180.1@1556.79,1048.33
  TOP w5: R197.1@2580.99,1959 2581.5,1959 v1(2617,1923.5)
  L3 w5: v1(306,997) 439.03,997 477.59,1035.57 704.69,1035.57 745.86,1076.74 820.17,1076.74 839.46,1057.45 929.29,1057.45 937.83,1065.99 v1(1323.73,1065.99) ; v1(1316,213) 1422.25,106.75 1810.03,106.75 1897.2,193.92 2029.48,193.92 2173.5,337.94 2173.5,690.19 2337.46,854.14 2347.98,854.14 2429.64,935.8 2570.7,935.8 2724.17,1089.27 2724.17,1816.33 v1(2617,1923.5)
  BOTTOM w4: v1(570,2088.5) 590,2068.5 590,1952.94 622.85,1920.09 747.89,1920.09 877.19,1790.79 877.19,1647.21 964.1,1560.3 1078.67,1560.3 1099.12,1539.86 1099.12,1302.8 1122.64,1279.29 1122.64,1167.58 1132,1158.22 1132,1137.08 1096.8,1101.88 1096.8,943.7 v1(1115,925.5) ; v1(1162,424) 1205.85,380.15 1321.42,380.15 1366.95,334.62 1366.95,263.93 1406,224.88 1406,174.48 R163.1@1390.25,158.73 1390.25,157.25 1376,143 1342.01,143 1335,150.01 1335,163.12 1315.37,182.75 R171.1@1315.37,187.47 1315.37,212.37 v1(1316,213) ; v1(1323.73,1065.99) 1324.43,1066.69 R144.1@1355.79,1066.69 1373.48,1049 1391,1049 1407,1065 v1(1408,1065)
AR_SDA: R23.1 R146.2 R162.1 R170.1 R182.2 R186.2 R198.1 | length 7500.3
  TOP w4: R186.2@284.77,973.33 323,935.1 v1(323,899) ; R23.1@585.61,2142.71 586.85,2142.71 611,2118.56 v1(611,2087.5) ; v1(1117,964.5) 1164.42,964.5 v1(1322.31,1122.39) 1345.17,1099.53 1345.17,1056.68 1276.07,987.58 1276.07,661.53 1160.53,546 1124.64,546 1111.72,533.09 1111.72,459.49 1127.38,443.83 1188.17,443.83 v1(1201.5,430.5) ; v1(1410.36,1119.51) 1428.74,1101.13 1428.74,1053.43 1421.2,1045.89 1421.2,1026.75 1433.22,1014.74 1451.18,1014.74 1490,1053.55 1490,1080.13 1529.95,1120.07 1673.37,1120.07 R182.2@1684.67,1108.77
  TOP w5: R198.1@2580.99,1922 2580.99,1920.51 v1(2619,1882.5)
  L3 w5: v1(323,899) 346,922 746.01,922 785.55,961.55 785.55,994.57 834.79,1043.8 1037.7,1043.8 v1(1117,964.5) ; v1(1472.74,127.45) 1802.5,127.45 1892.02,216.97 2033.48,216.97 2158.33,341.81 2158.33,719.56 2393.06,954.29 2566.32,954.29 2706.86,1094.83 2706.86,1794.64 v1(2619,1882.5)
  BOTTOM w4: v1(611,2087.5) 628.2,2104.7 734.71,2104.7 773.62,2065.78 773.62,1974.98 907.81,1840.79 907.81,1697.72 948.69,1656.85 948.69,1651.24 988.02,1611.91 1064.8,1611.91 1117.12,1559.59 1117.12,1340.79 1163.16,1294.76 1163.16,1254.64 1135.37,1226.86 1135.37,1170.4 1141.96,1163.81 1141.96,1131.48 1117,1106.52 v1(1117,964.5) ; v1(1201.5,430.5) 1235.5,396.5 1328.32,396.5 1380.18,344.64 1380.18,270.57 1428.02,222.73 R170.1@1428.02,187.47 1428.02,182.75 1429.74,182.75 1453.2,159.29 R162.1@1469.12,159.29 ; v1@1322.35,1122.39 1339.69,1105.05 1349.93,1105.05 R146.2@1355.79,1099.19 1376.11,1119.51 v1(1410.36,1119.51) ; R162.1@1470.25,159.29 1472.74,156.79 v1(1472.74,127.45)
AR_SPICLK1: U2.R9 U13.7 | length 3695.9
  TOP w4: v1(1012.56,1199.34) U13.7@1044.61,1199.34 ; v1(2250.82,2093.98) 2281.38,2063.42 2281.38,1812.59 2277.78,1808.99 2277.78,1679.54 2268.96,1670.72 U2.R9@2268.96,1657.03
  L3 w4: v1(1012.56,1199.34) 1037.14,1199.34 1069.98,1166.5 v1(1361.5,1166.5)
  L4 w5: v1(1361.5,1166.5) 1361.5,1221.2 1390.05,1249.75 1390.05,1298.28 1674.77,1583 1745.31,1583 1787.06,1624.74 1787.06,1708.88 1929.86,1851.68 1929.86,2108.76 1955.43,2134.33 2152.03,2134.33 2161.85,2144.15 2161.85,2172.92 2153.02,2181.75 1940.76,2181.75 1930.19,2192.32 1930.19,2224.76 1939.71,2234.27 2150.36,2234.27 2161.08,2245 2161.08,2273.89 2151.96,2283.01 1940.25,2283.01 1929.86,2293.41 1929.86,2315.34 1942.45,2327.93 2234.5,2327.93 2250.82,2311.61 v1(2250.82,2093.98)
AR_SYNC_IN: R62.2 R165.1 R196.2 U2.N10 | length 3578.6
  TOP w4: R62.2@929.85,1598.73 939.23,1598.73 946,1605.5 946,1635.83 971,1660.83 v1(971,1679.5) ; U2.N10@2243.37,1605.85 2243.37,1604.13 2256,1591.5 2256,1562.39 v1(2267.19,1551.2)
  L3 w5: v1(971,1679.5) 1008.47,1716.97 1078.45,1716.97 1085.73,1709.7 1213.92,1709.7 1441.22,1482.4 1811.68,1482.4 1874.35,1545.07 2114.72,1545.07 2178.75,1609.1 2238.56,1609.1 2255,1592.66 2255,1563.39 v1(2267.19,1551.2)
  L4 w5: v1(816,460.5) 816,592.5 v1(908,684.5)
  BOTTOM w4: v1(816,460.5) 816,459.5 884,391.5 884,228.51 913.68,198.83 913.68,175.8 R165.1@932.75,156.73 ; v1(908,684.5) 937.49,684.5 1192.06,939.07 1192.06,1091.33 1201.27,1100.54 1201.27,1241.71 1185.32,1257.66 1185.32,1327.91 1135.12,1378.11 1135.12,1580.67 1059.64,1656.15 994.35,1656.15 v1(971,1679.5) R196.2@971,1706.22
AR_SYNC_OUT_SOP1: R108.2 R113.1 U2.P11 | length 3694.5
  TOP w4: R113.1@608.92,428.65 629.99,407.58 1056.41,407.58 1068.52,395.47 1195.46,395.47 1312.06,512.07 R108.2@1330.35,512.07 1335.74,517.46 v1(1335.74,628.41) ; v1(2177,1852.5) 2237.31,1792.19 2237.31,1706.07 2205.28,1674.04 2205.28,1643.94 U2.P11@2217.78,1631.44
  L3 w5: v1(1422,1934.5) 1422,1937.93 1457.57,1973.5 1464.51,1973.5 1495.6,2004.6 1552.25,2004.6 1586.13,1970.72 1726.96,1970.72 1803.71,2047.46 1945.82,2047.46 2140.78,1852.5 v1(2177,1852.5)
  BOTTOM w4: v1(1335.74,628.41) 1302.51,628.41 1214.06,716.86 1214.06,1076.8 1223.27,1086.01 1223.27,1250.83 1208.8,1265.29 1208.8,1353.38 1186.39,1375.79 1186.39,1591.46 1150.92,1626.93 1150.92,1822.81 1262.61,1934.5 v1(1422,1934.5)
AR_TCK: R66.2 R70.1 U2.M13 | length 1383.3
  TOP w4: v1(1087,1662.5) 1107.67,1641.83 1107.67,1612.54 1091.75,1596.62 1091.75,1565.13 R70.1@1091.33,1564.71 ; U2.M13@2166.6,1580.26 2167.11,1579.75 v1(2185.79,1579.75)
  L3 w5: v1(1087,1662.5) 1117.67,1693.17 1202.26,1693.17 1427.16,1468.27 1825.77,1468.27 1885.83,1528.34 2134.38,1528.34 v1(2185.79,1579.75)
AR_TDI: R29.1 R30.1 U2.H13 | length 2126
  TOP w4: R29.1@963.83,2142.71 R30.1@995.75,2142.71 995.75,2165.75 993.09,2168.42 v1(979.57,2168.42) ; U2.H13@2166.6,1477.9 2182.84,1477.9 v1(2185.79,1474.95)
  L3 w5: v1(923,1654.5) 923,1632.13 995.32,1559.81 1256.15,1559.81 1390.85,1425.1 1864.04,1425.1 1913.89,1474.95 v1(2185.79,1474.95)
  L4 w5: v1(923,1654.5) 828.72,1748.78 828.72,1842.17 796.9,1873.99 796.9,1956.26 910.68,2070.03 910.68,2099.52 v1(979.57,2168.42)
AR_TDO_SOP0: R67.2 R71.1 R89.1 U2.J13 | length 2319.1
  TOP w4: R89.1@982.66,778.53 v1(1003.18,799.05) ; v1(1056.61,1518.55) 1069.65,1518.55 1076.01,1512.2 1125.02,1512.2 1139.6,1526.77 1139.6,1550.68 1124.25,1566.03 R67.2@1124.25,1598.73 1145.06,1598.73 1183.5,1637.17 v1(1183.5,1659.5) ; U2.J13@2166.6,1503.49 2218.63,1503.49 v1(2220.59,1505.45)
  L3 w5: v1(1183.5,1659.5) 1405.55,1437.45 1848.97,1437.45 1902.58,1491.06 2159.47,1491.06 2173.86,1505.45 v1(2220.59,1505.45)
  BOTTOM w4: v1(1003.18,799.05) 1085.8,881.67 1085.8,1116.37 1091.48,1122.05 1091.48,1148.61 1008.22,1231.87 1008.22,1470.17 v1(1056.61,1518.55)
AR_TMS: R65.2 R69.1 U2.L13 | length 1538.5
  TOP w4: v1(1004,1580.5) 1041.02,1580.5 R65.2@1059.25,1598.73 1059.25,1565.78 R69.1@1057.09,1563.62 ; U2.L13@2166.6,1554.67 2213.17,1554.67 v1(2215.99,1551.85)
  L3 w5: v1(1004,1580.5) 1060.57,1580.5 1159.8,1679.73 1192.06,1679.73 1420.17,1451.62 1835.73,1451.62 1892.37,1508.26 2138.54,1508.26 2182.14,1551.85 v1(2215.99,1551.85)
AR_VBGAP: C56.1 U2.B10 | length 89.4
  TOP w15: v1(2225.2,1345.25) 2243.37,1327.08 U2.B10@2243.37,1324.36
  BOTTOM w20: C56.1@2177.45,1313.3 2193.25,1313.3 v1(2225.2,1345.25)
AR_VOUT_PA: C10.1 C65.1 C83.1 R137.2 U2.A2 U2.B2
  other v1: 2524,1166 2528,1197
AR_VSENSE: P1.1 U2.C14 | length 2436.7
  TOP w4: U2.C14@2141.01,1349.95 v1(2141.01,1375.5)
  L3 w5: P1.1@31.27,1775.06 96.11,1710.22 96.11,1532.91 209.26,1419.76 390.75,1419.76 408.28,1402.24 1357.22,1402.24 1366.11,1393.35 1885.52,1393.35 1924.15,1431.98 2084.53,1431.98 v1(2141.01,1375.5)
AR_WARMRST: DS5.2 R15.1 R18.1 U2.N12 | length 3916.6
  TOP w4: DS5.2@33.45,304.13 v1(33.45,334.51) ; R15.1@1023.12,2179.56 R15.1@1024.12,2178.56 ; R18.1@1028.21,2143.06 1024.12,2147.15 R15.1@1024.12,2178.56 ; v1(1136.71,2106.17) 1136.71,2127.09 1101.9,2161.9 1040.78,2161.9 R15.1@1024.12,2178.56 ; v1(2073.23,1777.05) 2063.86,1767.68 2063.86,1724.36 2077.9,1710.32 2079.53,1710.32 2128.05,1661.79 2128.05,1652.31 2136.41,1643.95 2146.18,1643.95 2153.89,1636.24 2153.89,1626.47 2161.91,1618.45 2179.59,1618.45 U2.N12@2192.19,1605.85
  L3 w5: v1(1136.71,2106.17) 1234.35,2008.53 1290.53,2008.53 1389.61,1909.45 1426.71,1909.45 1444.06,1926.8 1475.57,1926.8 1493.96,1945.18 1687.91,1945.18 1856.03,1777.05 v1(2073.23,1777.05)
  L4 w5: v1(33.45,334.51) 77.03,334.51 179.25,436.73 213.04,436.73 328.88,552.57 328.88,865.35 361.69,898.16 361.69,1119.23 745.91,1503.45 827.65,1503.45 1003.71,1679.5 1003.71,1721.84 1153.48,1871.61 1153.48,2034.21 1164.69,2045.42 1164.69,2078.19 v1(1136.71,2106.17)
AR_XTALM: C9.1 U2.F14 Y1.3 | length 304.7
  TOP w4: C9.1@1893.4,1344.83 1920.93,1344.83 Y1.3@1942.3,1323.46 1942.3,1332.8 1977,1367.5 2043.53,1367.5 2092.52,1416.48 2130.77,1416.48 U2.F14@2141.01,1426.72
AR_XTALP: C15.2 U2.E14 Y1.1 | length 308.3
  TOP w4: C15.2@2027.09,1178.2 2027.09,1226.86 Y1.1@2015.14,1238.82 2015.14,1245.64 2067,1297.5 2067,1375.41 2079.69,1388.1 2121.6,1388.1 2134.63,1401.13 U2.E14@2141.01,1401.13
CAN_RX: R12.1 U13.3 | length 131.9
  TOP w4: R12.1@1015.51,1137.68 1037.61,1159.78 v1(1041.98,1159.78) ; v1(1083.98,1209.95) U13.3@1083.98,1238.71
  L4 w4: v1(1041.98,1159.78) 1062.37,1180.17 1062.37,1188.33 v1(1083.98,1209.95)
CAN_TX: R11.1 U13.16 | length 55.4
  TOP w4: U13.16@1139.1,1230.83 1147.47,1230.83 1153.56,1236.92 1153.56,1240.8 R11.1@1176.91,1264.15 ; R11.1@1175.84,1265.22 R11.1@1176.9,1266.28
CS1: R1.2 R14.1 R17.1 U13.11 | length 2898.2
  TOP w4: R14.1@638.26,2234.75 666.51,2263 v1(671.5,2263) 704.77,2229.73 R1.2@730.05,2229.73 ; R17.1@1060.25,2143.71 v1(1085.38,2143.71) ; U13.11@1099.73,1175.71 1099.73,1157.63 v1(1111.78,1145.58)
  L3 w5: v1(671.5,2263) 653.64,2263 625.73,2235.1 625.73,2175.02 662.95,2137.8 887.98,2137.8 913.59,2163.41 952.06,2163.41 971.76,2143.71 v1(1085.38,2143.71)
  L4 w5: v1(671.5,2263) 717.97,2216.53 717.97,2160.53 758.18,2120.32 758.18,2047.08 746.05,2034.96 571.28,2034.96 564.44,2028.12 564.44,2004.37 570.98,1997.83 732.82,1997.83 739.99,1990.66 739.99,1966.97 732.16,1959.14 571.26,1959.14 564.44,1952.33 564.44,1929.79 572.07,1922.16 716.18,1922.16 727.08,1911.26 v1(727.08,1845.55)
  BOTTOM w4: v1(727.08,1845.55) 844.38,1728.26 844.38,1624.18 928.2,1540.37 1063.08,1540.37 1079.84,1523.61 1079.84,1485.5 1020.85,1426.52 1020.85,1236.69 1069.89,1187.65 1069.89,1187.47 v1(1111.78,1145.58)
D_LOGGER: J6.6 R1.1 | length 213.3
  TOP w4: R1.1@730.05,2255.71 v1(730.05,2290.45)
  BOTTOM w4: J6.6@727.5,2220.72 727.5,2246.44 689.53,2284.41 673.17,2284.41 669.5,2288.08 669.5,2299.16 672.3,2301.95 718.55,2301.95 v1(730.05,2290.45)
